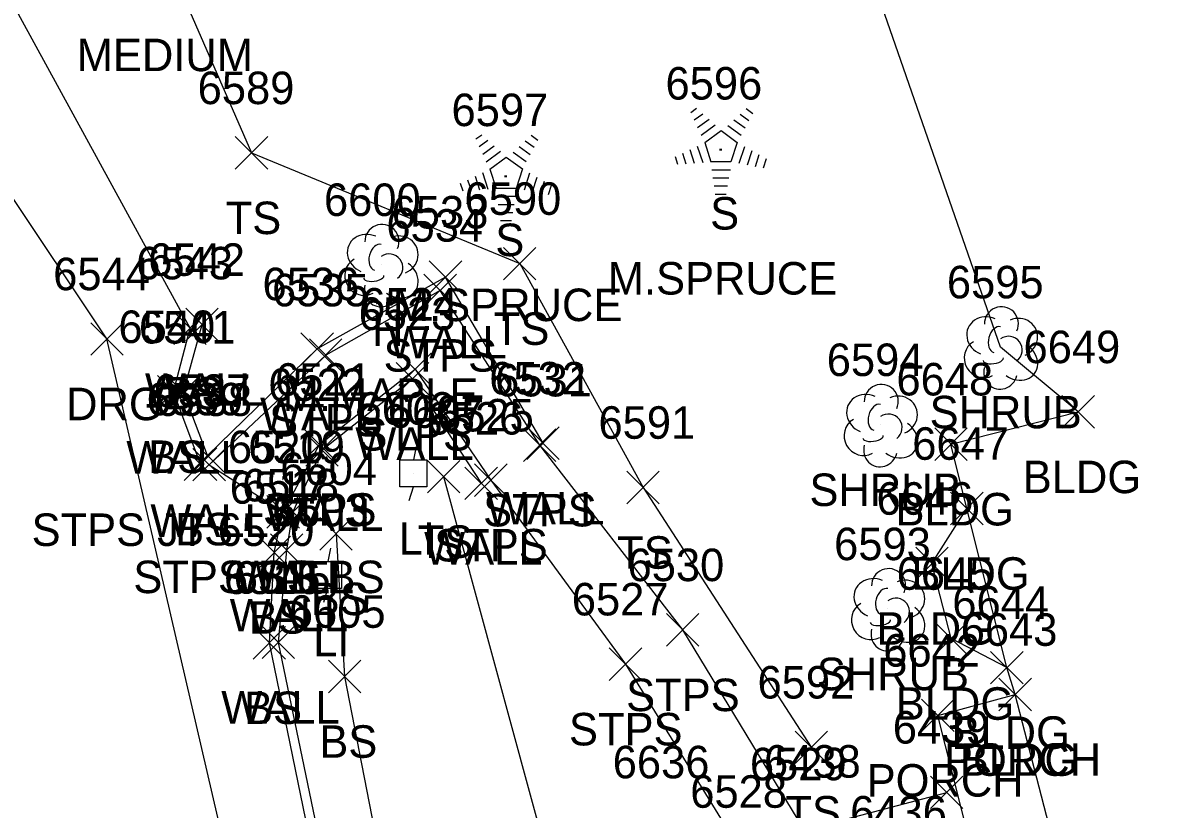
# Model space of a CAD drawing. Extents: x 1769141 to 1770911, y 735471 to 741449.
# Drawn here: x 1770229.3 to 1770299, y 740823.1 to 740871.5 of the extents above; entities that cross this region are included whole.
import ezdxf

# ---------------------------------------------------------------- set-up
doc = ezdxf.new("R2010")
doc.units = 0
for name, color, linetype in [('L_A', 7, 'Continuous'), ('L_C', 7, 'Continuous'), ('L_I', 7, 'Continuous'), ('L_TIC', 7, 'Continuous'), ('LBC', 7, 'Continuous'), ('LBF', 7, 'Continuous'), ('LELB', 7, 'Continuous'), ('LSH', 7, 'Continuous'), ('LSOGP', 7, 'Continuous'), ('LTC', 7, 'Continuous'), ('LTD', 7, 'Continuous'), ('LW', 7, 'Continuous'), ('R_A', 7, 'Continuous'), ('R_I', 7, 'Continuous'), ('R_TIC', 7, 'Continuous'), ('RDG', 7, 'Continuous'), ('U_A', 7, 'Continuous'), ('U_I', 7, 'Continuous'), ('ULP', 7, 'Continuous')]:
    doc.layers.add(name, color=color, linetype=linetype)

msp = doc.modelspace()

# ---------------------------------------------------------------- linework, layer by layer
at = {"layer": 'L_TIC'}
for points in [[(1770242.383, 740862.511), (1770244.383, 740864.511)], [(1770244.383, 740862.511), (1770242.383, 740864.511)], [(1770258.878, 740855.695), (1770260.878, 740857.695)], [(1770260.878, 740855.695), (1770258.878, 740857.695)], [(1770254.309, 740854.858), (1770256.309, 740856.858)], [(1770256.309, 740854.858), (1770254.309, 740856.858)], [(1770253.984, 740854.047), (1770255.984, 740856.047)], [(1770255.984, 740854.047), (1770253.984, 740856.047)], [(1770239.338, 740851.943), (1770241.338, 740853.943)], [(1770241.338, 740851.943), (1770239.338, 740853.943)], [(1770238.598, 740851.724), (1770240.598, 740853.724)], [(1770240.598, 740851.724), (1770238.598, 740853.724)], [(1770246.419, 740850.443), (1770248.419, 740852.443)], [(1770248.419, 740850.443), (1770246.419, 740852.443)], [(1770246.946, 740850.065), (1770248.946, 740852.065)], [(1770248.946, 740850.065), (1770246.946, 740852.065)], [(1770252.438, 740849.19), (1770254.438, 740851.19)], [(1770254.438, 740849.19), (1770252.438, 740851.19)], [(1770252.279, 740848.615), (1770254.279, 740850.615)], [(1770254.279, 740848.615), (1770252.279, 740850.615)], [(1770237.589, 740847.809), (1770239.589, 740849.809)], [(1770239.589, 740847.809), (1770237.589, 740849.809)], [(1770238.192, 740847.776), (1770240.192, 740849.776)], [(1770240.192, 740847.776), (1770238.192, 740849.776)], [(1770293.231, 740846.568), (1770295.231, 740848.568)], [(1770295.231, 740846.568), (1770293.231, 740848.568)], [(1770246.569, 740844.563), (1770248.569, 740846.563)], [(1770248.569, 740844.563), (1770246.569, 740846.563)], [(1770246.72, 740844.239), (1770248.72, 740846.239)], [(1770248.72, 740844.239), (1770246.72, 740846.239)], [(1770260.108, 740844.521), (1770262.108, 740846.521)], [(1770262.108, 740844.521), (1770260.108, 740846.521)], [(1770260.313, 740844.643), (1770262.313, 740846.643)], [(1770262.313, 740844.643), (1770260.313, 740846.643)], [(1770285.406, 740844.581), (1770287.406, 740846.581)], [(1770287.406, 740844.581), (1770285.406, 740846.581)], [(1770239.672, 740843.879), (1770241.672, 740845.879)], [(1770241.672, 740843.879), (1770239.672, 740845.879)], [(1770239.242, 740843.356), (1770241.242, 740845.356)], [(1770241.242, 740843.356), (1770239.242, 740845.356)], [(1770239.775, 740843.318), (1770241.775, 740845.318)], [(1770241.775, 740843.318), (1770239.775, 740845.318)], [(1770254.198, 740842.585), (1770256.198, 740844.585)], [(1770256.198, 740842.585), (1770254.198, 740844.585)], [(1770256.51, 740842.175), (1770258.51, 740844.175)], [(1770258.51, 740842.175), (1770256.51, 740844.175)], [(1770257.102, 740842.366), (1770259.102, 740844.366)], [(1770259.102, 740842.366), (1770257.102, 740844.366)], [(1770266.465, 740841.916), (1770268.465, 740843.916)], [(1770268.465, 740841.916), (1770266.465, 740843.916)], [(1770244.325, 740840.415), (1770246.325, 740842.415)], [(1770246.325, 740840.415), (1770244.325, 740842.415)], [(1770244.325, 740840.415), (1770246.325, 740842.415)], [(1770246.325, 740840.415), (1770244.325, 740842.415)], [(1770244.926, 740840.408), (1770246.926, 740842.408)], [(1770246.926, 740840.408), (1770244.926, 740842.408)], [(1770286.378, 740840.622), (1770288.378, 740842.622)], [(1770288.378, 740840.622), (1770286.378, 740842.622)], [(1770247.583, 740839.061), (1770249.583, 740841.061)], [(1770249.583, 740839.061), (1770247.583, 740841.061)], [(1770243.781, 740837.92), (1770245.781, 740839.92)], [(1770245.781, 740837.92), (1770243.781, 740839.92)], [(1770244.547, 740838.06), (1770246.547, 740840.06)], [(1770246.547, 740838.06), (1770244.547, 740840.06)], [(1770284.236, 740837.24), (1770286.236, 740839.24)], [(1770286.236, 740837.24), (1770284.236, 740839.24)], [(1770268.905, 740833.153), (1770270.905, 740835.153)], [(1770270.905, 740833.153), (1770268.905, 740835.153)], [(1770243.481, 740832.358), (1770245.481, 740834.358)], [(1770245.481, 740832.358), (1770243.481, 740834.358)], [(1770244.032, 740832.383), (1770246.032, 740834.383)], [(1770246.032, 740832.383), (1770244.032, 740834.383)], [(1770285.419, 740832.621), (1770287.419, 740834.621)], [(1770287.419, 740832.621), (1770285.419, 740834.621)], [(1770265.39, 740831.043), (1770267.39, 740833.043)], [(1770267.39, 740831.043), (1770265.39, 740833.043)], [(1770248.111, 740830.282), (1770250.111, 740832.282)], [(1770250.111, 740830.282), (1770248.111, 740832.282)], [(1770288.843, 740830.832), (1770290.843, 740832.832)], [(1770290.843, 740830.832), (1770288.843, 740832.832)], [(1770289.358, 740829.172), (1770291.358, 740831.172)], [(1770291.358, 740829.172), (1770289.358, 740831.172)], [(1770289.358, 740829.172), (1770291.358, 740831.172)], [(1770291.358, 740829.172), (1770289.358, 740831.172)], [(1770284.596, 740827.891), (1770286.596, 740829.891)], [(1770286.596, 740827.891), (1770284.596, 740829.891)], [(1770276.815, 740825.928), (1770278.815, 740827.928)], [(1770278.815, 740825.928), (1770276.815, 740827.928)], [(1770285.142, 740823.155), (1770287.142, 740825.155)], [(1770287.142, 740823.155), (1770285.142, 740825.155)]]:
    msp.add_lwpolyline(points, dxfattribs=at)
at = {"layer": 'LBC'}
msp.add_lwpolyline([(1770319.128, 740806.628), (1770297.879, 740801.102), (1770296.632, 740805.083), (1770293.266, 740806.948), (1770292.047, 740811.449), (1770294.139, 740814.916), (1770293.756, 740817.035), (1770290.358, 740830.172), (1770289.843, 740831.832), (1770286.419, 740833.621), (1770285.236, 740838.24), (1770287.378, 740841.622), (1770286.406, 740845.581), (1770294.231, 740847.568)], dxfattribs=at)
at = {"layer": 'LBF'}
for points in [[(1770245.325, 740841.415), (1770247.569, 740845.563), (1770253.438, 740850.19), (1770258.102, 740843.366), (1770266.39, 740832.043), (1770273.678, 740820.206), (1770277.355, 740821.898), (1770269.905, 740834.153), (1770261.108, 740845.521), (1770254.984, 740855.047), (1770247.946, 740851.065), (1770240.775, 740844.318)], [(1770240.775, 740844.318), (1770245.325, 740841.415)], [(1770293.756, 740817.035), (1770288.955, 740815.572), (1770285.596, 740828.891), (1770290.358, 740830.172)], [(1770289.268, 740814.772), (1770292.85, 740800.446), (1770288.64, 740799.039), (1770283.566, 740818.929), (1770279.169, 740818.012), (1770278.212, 740822.06), (1770286.142, 740824.155)]]:
    msp.add_lwpolyline(points, dxfattribs=at)
at = {"layer": 'LELB'}
for points in [[(1770206.325, 740923.12), (1770218.826, 740907.514), (1770232.554, 740888.353), (1770243.383, 740863.511), (1770259.878, 740856.695), (1770267.465, 740842.916), (1770277.815, 740826.928)], [(1770240.242, 740844.356), (1770238.589, 740848.809), (1770239.598, 740852.724), (1770226.756, 740876.232), (1770210.967, 740892.635), (1770189.956, 740913.809)], [(1770255.198, 740843.585), (1770262.583, 740816.387), (1770260.091, 740813.303)], [(1770333.692, 740767.829), (1770307.925, 740759.691), (1770284.172, 740751.04), (1770275.373, 740749.173), (1770270.306, 740749.99), (1770266.387, 740754.529), (1770256.269, 740784.114), (1770249.122, 740810.772), (1770244.481, 740833.358), (1770244.781, 740838.92), (1770245.325, 740841.415)], [(1770248.583, 740840.061), (1770249.111, 740831.282), (1770252.587, 740813.383)]]:
    msp.add_lwpolyline(points, dxfattribs=at)
at = {"layer": 'LSH'}
for p, q in [((1770289.463, 740851.557), (1770289.463, 740851.557)), ((1770289.463, 740851.557), (1770289.463, 740851.557)), ((1770282.072, 740846.776), (1770282.072, 740846.776)), ((1770282.072, 740846.776), (1770282.072, 740846.776)), ((1770282.524, 740835.443), (1770282.524, 740835.443)), ((1770282.524, 740835.443), (1770282.524, 740835.443))]:
    msp.add_line(p, q, dxfattribs=at)
for centre in [(1770289.51, 740852.991), (1770282.118, 740848.21), (1770282.57, 740836.876)]:
    msp.add_arc(centre, 1.047, 335.52715, 180.95627, dxfattribs=at)
for centre, major_axis, ratio, start_param, end_param in [((1770288.671, 740852.223), (1.21, -0.512), 0.895232, 1.570796, 4.712389), ((1770290.504, 740852.14), (-1.141, -0.483), 0.949671, 1.570796, 4.712389), ((1770289.254, 740852.015), (-0.208, -0.792), 0.645439, 3.141593, 6.283185), ((1770288.38, 740850.848), (0.584, -1.042), 0.959034, 3.141593, 6.283185), ((1770289.963, 740851.39), (-0.5, 0.667), 0.989748, 3.141593, 6.283185), ((1770290.463, 740850.724), (-1.09, 0.792), 0.841452, 1.570796, 4.712389), ((1770289.005, 740850.807), (-0.625, -0.083), 0.423636, 0, 3.141593), ((1770289.463, 740850.057), (0.265, 1.061), 0.942809, 1.570796, 4.712389), ((1770281.28, 740847.442), (1.21, -0.512), 0.895232, 1.570796, 4.712389), ((1770283.113, 740847.359), (-1.141, -0.483), 0.949671, 1.570796, 4.712389), ((1770281.863, 740847.234), (-0.208, -0.792), 0.645439, 3.141593, 6.283185), ((1770280.988, 740846.067), (0.584, -1.042), 0.959034, 3.141593, 6.283185), ((1770282.572, 740846.609), (-0.5, 0.667), 0.989748, 3.141593, 6.283185), ((1770283.072, 740845.943), (-1.09, 0.792), 0.841452, 1.570796, 4.712389), ((1770282.072, 740845.276), (0.265, 1.061), 0.942809, 1.570796, 4.712389), ((1770281.613, 740846.026), (-0.625, -0.083), 0.423636, 0, 3.141593), ((1770281.732, 740836.109), (1.21, -0.512), 0.895232, 1.570796, 4.712389), ((1770283.565, 740836.026), (-1.141, -0.483), 0.949671, 1.570796, 4.712389), ((1770282.315, 740835.901), (-0.208, -0.792), 0.645439, 3.141593, 6.283185), ((1770281.44, 740834.734), (0.584, -1.042), 0.959034, 3.141593, 6.283185), ((1770283.024, 740835.276), (-0.5, 0.667), 0.989748, 3.141593, 6.283185), ((1770283.524, 740834.609), (-1.09, 0.792), 0.841452, 1.570796, 4.712389), ((1770282.065, 740834.692), (-0.625, -0.083), 0.423636, 0, 3.141593), ((1770282.524, 740833.943), (0.265, 1.061), 0.942809, 1.570796, 4.712389)]:
    msp.add_ellipse(centre, major_axis=major_axis, ratio=ratio, start_param=start_param, end_param=end_param, dxfattribs=at)
at = {"layer": 'LSOGP'}
msp.add_lwpolyline([(1770326.749, 740777.797), (1770321.91, 740797.701), (1770321.183, 740802.043), (1770319.128, 740806.628), (1770297.879, 740801.102), (1770296.632, 740805.083), (1770294.139, 740814.916), (1770293.756, 740817.035), (1770290.358, 740830.172), (1770289.843, 740831.832), (1770287.378, 740841.622), (1770286.406, 740845.581), (1770294.231, 740847.568), (1770289.463, 740851.557), (1770273.233, 740898.25), (1770261.014, 740930.952), (1770256.423, 740947.489)], dxfattribs=at)
at = {"layer": 'LTC'}
for p, q in [((1770270.403, 740866), (1770270.758, 740866.257)), ((1770270.613, 740865.534), (1770271.142, 740865.918)), ((1770273.43, 740865.892), (1770273.98, 740865.493)), ((1770273.802, 740866.24), (1770274.221, 740865.936)), ((1770270.822, 740865.068), (1770271.526, 740865.58)), ((1770271.032, 740864.603), (1770271.91, 740865.241)), ((1770272.688, 740865.195), (1770273.498, 740864.606)), ((1770273.059, 740865.543), (1770273.739, 740865.05)), ((1770257.185, 740864.365), (1770257.54, 740864.623)), ((1770260.584, 740864.606), (1770261.003, 740864.301)), ((1770271.257, 740864.148), (1770272.268, 740864.882)), ((1770272.268, 740864.882), (1770273.265, 740864.157)), ((1770257.395, 740863.9), (1770257.924, 740864.284)), ((1770257.605, 740863.434), (1770258.308, 740863.945)), ((1770257.814, 740862.968), (1770258.692, 740863.606)), ((1770259.842, 740863.909), (1770260.521, 740863.415)), ((1770260.212, 740864.257), (1770260.762, 740863.858)), ((1770270.347, 740863.712), (1770270.618, 740862.877)), ((1770270.802, 740863.928), (1770271.133, 740862.909)), ((1770271.257, 740864.148), (1770271.644, 740862.954)), ((1770273.265, 740864.157), (1770272.874, 740862.954)), ((1770273.703, 740863.886), (1770273.365, 740862.847)), ((1770274.147, 740863.636), (1770273.86, 740862.751)), ((1770258.039, 740862.513), (1770259.05, 740863.248)), ((1770259.05, 740863.248), (1770260.047, 740862.523)), ((1770259.47, 740863.561), (1770260.28, 740862.972)), ((1770269.436, 740863.279), (1770269.588, 740862.811)), ((1770269.891, 740863.496), (1770270.103, 740862.844)), ((1770272.874, 740862.954), (1770271.644, 740862.954)), ((1770274.592, 740863.386), (1770274.355, 740862.656)), ((1770275.036, 740863.136), (1770274.849, 740862.561)), ((1770257.584, 740862.294), (1770257.915, 740861.275)), ((1770258.039, 740862.513), (1770258.426, 740861.32)), ((1770260.047, 740862.523), (1770259.656, 740861.32)), ((1770260.485, 740862.252), (1770260.147, 740861.212)), ((1770272.836, 740862.454), (1770271.691, 740862.454)), ((1770256.218, 740861.644), (1770256.37, 740861.176)), ((1770256.673, 740861.861), (1770256.885, 740861.209)), ((1770257.129, 740862.078), (1770257.4, 740861.242)), ((1770260.93, 740862.001), (1770260.642, 740861.117)), ((1770261.374, 740861.751), (1770261.137, 740861.022)), ((1770272.752, 740861.954), (1770271.764, 740861.954)), ((1770259.656, 740861.32), (1770258.426, 740861.32)), ((1770259.618, 740860.82), (1770258.473, 740860.82)), ((1770261.818, 740861.501), (1770261.632, 740860.927)), ((1770272.668, 740861.454), (1770271.837, 740861.454)), ((1770272.585, 740860.954), (1770271.91, 740860.954)), ((1770259.534, 740860.32), (1770258.546, 740860.32)), ((1770259.45, 740859.82), (1770258.619, 740859.82)), ((1770259.367, 740859.32), (1770258.692, 740859.32))]:
    msp.add_line(p, q, dxfattribs=at)
at = {"layer": 'LTD'}
msp.add_line((1770251.36, 740856.627), (1770251.36, 740856.627), dxfattribs=at)
msp.add_line((1770251.36, 740856.627), (1770251.36, 740856.627), dxfattribs=at)
msp.add_arc((1770251.406, 740858.061), 1.047, 335.52715, 180.95627, dxfattribs=at)
for centre, major_axis, ratio, start_param, end_param in [((1770250.568, 740857.294), (1.21, -0.512), 0.895232, 1.570796, 4.712389), ((1770252.401, 740857.211), (-1.141, -0.483), 0.949671, 1.570796, 4.712389), ((1770251.151, 740857.086), (-0.208, -0.792), 0.645439, 3.141593, 6.283185), ((1770251.86, 740856.461), (-0.5, 0.667), 0.989748, 3.141593, 6.283185), ((1770250.276, 740855.919), (0.584, -1.042), 0.959034, 3.141593, 6.283185), ((1770252.36, 740855.794), (-1.09, 0.792), 0.841452, 1.570796, 4.712389), ((1770250.901, 740855.877), (-0.625, -0.083), 0.423636, 0, 3.141593), ((1770251.36, 740855.127), (0.265, 1.061), 0.942809, 1.570796, 4.712389)]:
    msp.add_ellipse(centre, major_axis=major_axis, ratio=ratio, start_param=start_param, end_param=end_param, dxfattribs=at)
at = {"layer": 'LW'}
for points in [[(1770261.313, 740845.643), (1770255.309, 740855.858), (1770247.419, 740851.443), (1770240.672, 740844.879), (1770239.192, 740848.776), (1770240.338, 740852.943)], [(1770249.653, 740811.13), (1770245.032, 740833.383), (1770245.547, 740839.06), (1770245.926, 740841.408), (1770247.72, 740845.239), (1770253.279, 740849.615), (1770257.51, 740843.175)]]:
    msp.add_lwpolyline(points, dxfattribs=at)
at = {"layer": 'R_TIC'}
for points in [[(1770233.488, 740851.058), (1770235.488, 740853.058)], [(1770235.488, 740851.058), (1770233.488, 740853.058)]]:
    msp.add_lwpolyline(points, dxfattribs=at)
at = {"layer": 'RDG'}
msp.add_lwpolyline([(1770334.527, 740765.967), (1770308.335, 740757.217), (1770284.491, 740749.702), (1770275.242, 740747.93), (1770267.767, 740748.16), (1770256.736, 740754.841), (1770254.693, 740761.852), (1770251.123, 740783.798), (1770243.609, 740812.701), (1770234.488, 740852.058), (1770221.837, 740871.004), (1770206.748, 740889.326), (1770180.078, 740903.239)], dxfattribs=at)
at = {"layer": 'ULP'}
for p, q in [((1770253.503, 740845.449), (1770253.336, 740844.615)), ((1770252.503, 740842.949), (1770252.503, 740844.615)), ((1770252.503, 740844.615), (1770254.169, 740844.615)), ((1770254.169, 740844.615), (1770254.169, 740842.949)), ((1770253.336, 740843.782), (1770253.336, 740843.782)), ((1770254.169, 740842.949), (1770252.503, 740842.949)), ((1770253.086, 740842.115), (1770253.336, 740842.949)), ((1770248.243, 740839.192), (1770248.077, 740838.358)), ((1770247.243, 740836.692), (1770247.243, 740838.358)), ((1770247.243, 740838.358), (1770248.91, 740838.358)), ((1770248.91, 740838.358), (1770248.91, 740836.692)), ((1770248.077, 740837.525), (1770248.077, 740837.525)), ((1770248.91, 740836.692), (1770247.243, 740836.692)), ((1770247.827, 740835.858), (1770248.077, 740836.692))]:
    msp.add_line(p, q, dxfattribs=at)

# ---------------------------------------------------------------- texts
at = {"layer": 'L_A'}
for s, p in [('S', (1770271.594, 740858.792)), ('TS', (1770241.793, 740858.511)), ('S', (1770258.376, 740857.157)), ('H', (1770250.793, 740851.627)), ('TS', (1770258.287, 740851.695)), ('WALL', (1770251.797, 740850.858)), ('STPS', (1770251.504, 740850.047)), ('WALL', (1770236.826, 740847.943)), ('BS', (1770238.039, 740847.724)), ('WALL', (1770243.907, 740846.443)), ('SHRUB', (1770285.093, 740846.557)), ('STPS', (1770244.466, 740846.065)), ('STPS', (1770249.958, 740845.19)), ('WALL', (1770249.767, 740844.615)), ('WALL', (1770235.68, 740843.776)), ('BS', (1770237.03, 740843.809)), ('BLDG', (1770290.821, 740842.568)), ('SHRUB', (1770277.702, 740841.776)), ('STPS', (1770244.088, 740840.563)), ('WALL', (1770244.208, 740840.239)), ('STPS', (1770257.628, 740840.521)), ('WALL', (1770257.801, 740840.643)), ('BLDG', (1770282.996, 740840.581)), ('STPS JT 6520', (1770229.854, 740839.318)), ('WALL', (1770237.16, 740839.879)), ('BS', (1770238.683, 740839.356)), ('TS', (1770253.607, 740838.585)), ('WALL', (1770253.998, 740838.175)), ('STPS', (1770254.622, 740838.366)), ('TS', (1770265.874, 740837.916)), ('BLDG', (1770283.969, 740836.622)), ('STPS ST BS', (1770236.112, 740836.415)), ('WALL', (1770242.414, 740836.408)), ('BS', (1770243.766, 740836.415)), ('BS', (1770247.024, 740835.061)), ('WALL', (1770242.036, 740834.06)), ('BS', (1770243.222, 740833.92)), ('BLDG', (1770281.827, 740833.24)), ('SHRUB', (1770278.154, 740830.443)), ('STPS', (1770266.425, 740829.153)), ('WALL', (1770241.52, 740828.383)), ('BS', (1770242.922, 740828.358)), ('BLDG', (1770283.01, 740828.621)), ('STPS', (1770262.91, 740827.043)), ('BLDG', (1770286.434, 740826.832)), ('BS', (1770247.552, 740826.282)), ('PORCH', (1770285.98, 740825.172)), ('BLDG', (1770286.949, 740825.172)), ('PORCH', (1770281.218, 740823.891)), ('TS', (1770276.225, 740821.928))]:
    msp.add_text(s, height=2, dxfattribs=at).set_placement(p)
at = {"layer": 'L_C'}
for s, p in [('MEDIUM', (1770232.629, 740868.54)), ('M.SPRUCE', (1770265.295, 740854.792)), ('M.SPRUCE', (1770252.077, 740853.157)), ('M.MAPLE', (1770245.297, 740847.627))]:
    msp.add_text(s, height=2, dxfattribs=at).set_placement(p)
at = {"layer": 'L_I'}
for s, p in [('6589', (1770240.068, 740866.511)), ('6596', (1770268.846, 740866.792)), ('6597', (1770255.683, 740865.157)), ('6600', (1770247.84, 740859.627)), ('6590', (1770256.484, 740859.695)), ('6533', (1770252.001, 740858.858)), ('6534', (1770251.677, 740858.047)), ('6543', (1770236.291, 740855.724)), ('6542', (1770237.031, 740855.943)), ('6536', (1770244.057, 740854.443)), ('6535', (1770244.639, 740854.065)), ('6595', (1770286.156, 740854.557)), ('6523', (1770249.971, 740852.615)), ('6524', (1770250.131, 740853.19)), ('6540', (1770235.195, 740851.809)), ('6541', (1770236.452, 740851.776)), ('6649', (1770290.869, 740850.568)), ('6594', (1770278.765, 740849.776)), ('6521', (1770244.828, 740848.563)), ('6532', (1770258.006, 740848.643)), ('6531', (1770258.368, 740848.521)), ('6648', (1770283.052, 740848.581)), ('6537', (1770237.365, 740847.879)), ('6522', (1770244.412, 740848.239)), ('6539', (1770236.927, 740847.356)), ('6538', (1770237.468, 740847.318)), ('6607', (1770251.765, 740846.585)), ('6525', (1770254.795, 740846.366)), ('6526', (1770254.147, 740846.175)), ('6591', (1770264.724, 740845.916)), ('6520', (1770241.931, 740844.415)), ('6520', (1770241.931, 740844.415)), ('6519', (1770243.178, 740844.408)), ('6647', (1770284.024, 740844.622)), ('6604', (1770245.15, 740843.061)), ('6517', (1770242.041, 740841.92)), ('6518', (1770242.807, 740842.06)), ('6646', (1770281.827, 740841.24)), ('6593', (1770279.217, 740838.443)), ('6530', (1770266.511, 740837.153)), ('6645', (1770283.065, 740836.621)), ('6516', (1770241.685, 740836.358)), ('6515', (1770242.292, 740836.383)), ('6527', (1770263.083, 740835.043)), ('6644', (1770286.489, 740834.832)), ('6605', (1770245.678, 740834.282)), ('6643', (1770287.004, 740833.172)), ('6643', (1770287.004, 740833.172)), ('6642', (1770282.242, 740831.891)), ('6592', (1770274.508, 740829.928)), ('6439', (1770282.827, 740827.155)), ('6636', (1770265.599, 740825.019)), ('6529', (1770274.04, 740824.898)), ('6438', (1770274.905, 740825.06)), ('6528', (1770270.371, 740823.206)), ('6436', (1770280.204, 740821.929))]:
    msp.add_text(s, height=2, dxfattribs=at).set_placement(p)
at = {"layer": 'LTC'}
for p in [(1770272.151, 740863.896), (1770258.933, 740862.261)]:
    msp.add_text('.', height=1.037, rotation=270, dxfattribs=at).set_placement(p)
at = {"layer": 'R_A'}
msp.add_text('DRG', height=2, dxfattribs=at).set_placement((1770231.976, 740847.058))
at = {"layer": 'R_I'}
msp.add_text('6544', height=2, dxfattribs=at).set_placement((1770231.181, 740855.058))
at = {"layer": 'U_A'}
for p in [(1770252.438, 740838.782), (1770247.179, 740832.525)]:
    msp.add_text('LI', height=2, dxfattribs=at).set_placement(p)
at = {"layer": 'U_I'}
for s, p in [('6602', (1770249.903, 740846.782)), ('6603', (1770244.644, 740840.525))]:
    msp.add_text(s, height=2, dxfattribs=at).set_placement(p)

doc.saveas('drawing.dxf')
